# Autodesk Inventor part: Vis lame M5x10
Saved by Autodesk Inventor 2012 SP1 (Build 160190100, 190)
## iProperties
Created: 2014-12
Part Number: Vis lame M5x10
Material: Default
Document SubType Name: Modeling
Designer: Bruno
Density: 1 g/cm^3
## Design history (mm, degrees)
node "Vis lame M5x101"
node "Vis lame M5x10"
node "Base1"
